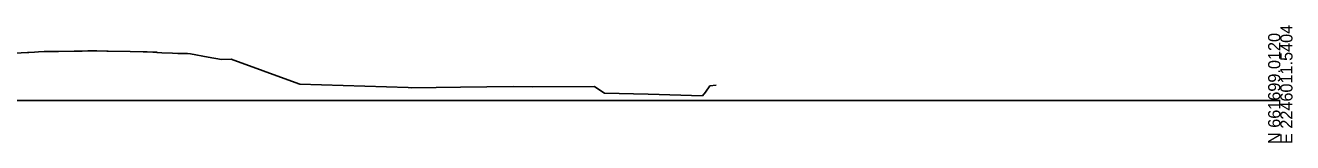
# Model space of a CAD drawing. Extents: x -26 to 603, y -10 to 9526.
# Drawn here: x 311.2 to 602.8, y 490.3 to 517.4 of the extents above; entities that cross this region are included whole.
import ezdxf

# ---------------------------------------------------------------- set-up
doc = ezdxf.new("R2010")
doc.units = 0
doc.layers.add('Exist Cross Section Cell', color=7, linetype='Continuous')
doc.layers.add('Exist XS Ground Line', color=7, linetype='Continuous')

msp = doc.modelspace()

# ---------------------------------------------------------------- linework, layer by layer
at = {"layer": 'Exist Cross Section Cell'}
msp.add_line((300, 500), (600, 500), dxfattribs=at)
at = {"layer": 'Exist XS Ground Line'}
for p, q in [((307.27, 510.85), (311.71, 511.1)), ((311.71, 511.1), (312.06, 511.13)), ((312.06, 511.13), (313.35, 511.2)), ((313.35, 511.2), (314.25, 511.25)), ((314.25, 511.25), (315.53, 511.33)), ((315.53, 511.33), (316, 511.32)), ((316, 511.32), (318.53, 511.35)), ((318.53, 511.35), (318.84, 511.35)), ((318.84, 511.35), (322.42, 511.4)), ((322.42, 511.4), (324.33, 511.43)), ((324.33, 511.43), (325.63, 511.45)), ((325.63, 511.45), (327, 511.48)), ((327, 511.48), (327.67, 511.47)), ((327.67, 511.47), (329.97, 511.42)), ((329.97, 511.42), (330.31, 511.41)), ((330.31, 511.41), (335.31, 511.32)), ((335.31, 511.32), (338.31, 511.29)), ((338.31, 511.29), (339.28, 511.28)), ((339.28, 511.28), (340.55, 511.19)), ((340.55, 511.19), (341.37, 511.17)), ((341.37, 511.17), (341.53, 511.12)), ((341.53, 511.12), (342.6, 511.05)), ((342.6, 511.05), (345.08, 510.93)), ((345.08, 510.93), (346.3, 510.89)), ((346.3, 510.89), (347.81, 510.84)), ((347.81, 510.84), (348.55, 510.85)), ((348.55, 510.85), (349.23, 510.82)), ((349.23, 510.82), (353.28, 510.01)), ((353.28, 510.01), (356.38, 509.49)), ((356.38, 509.49), (358.62, 509.53)), ((358.62, 509.53), (373.32, 504.22)), ((373.32, 504.22), (374.39, 503.84)), ((374.39, 503.84), (399.28, 503.01)), ((399.28, 503.01), (400.13, 502.99)), ((400.13, 502.99), (411.38, 503.09)), ((411.38, 503.09), (423.45, 503.24)), ((423.45, 503.24), (428.01, 503.22)), ((428.01, 503.22), (442.17, 503.25)), ((442.17, 503.25), (443.9, 502.11)), ((443.9, 502.11), (444.48, 501.72)), ((444.48, 501.72), (454.53, 501.49)), ((467.06, 501.1), (467.72, 501.99)), ((467.72, 501.99), (468.71, 503.45)), ((468.71, 503.45), (470.17, 503.61)), ((454.53, 501.49), (467.06, 501.1))]:
    msp.add_line(p, q, dxfattribs=at)

# ---------------------------------------------------------------- texts
at = {"layer": 'Exist Cross Section Cell'}
for s, p in [('E 2246011.5404', (602.8, 490)), ('N 661699.0120', (600, 490))]:
    msp.add_text(s, height=2.8, rotation=90, dxfattribs=at).set_placement(p)

doc.saveas('drawing.dxf')
